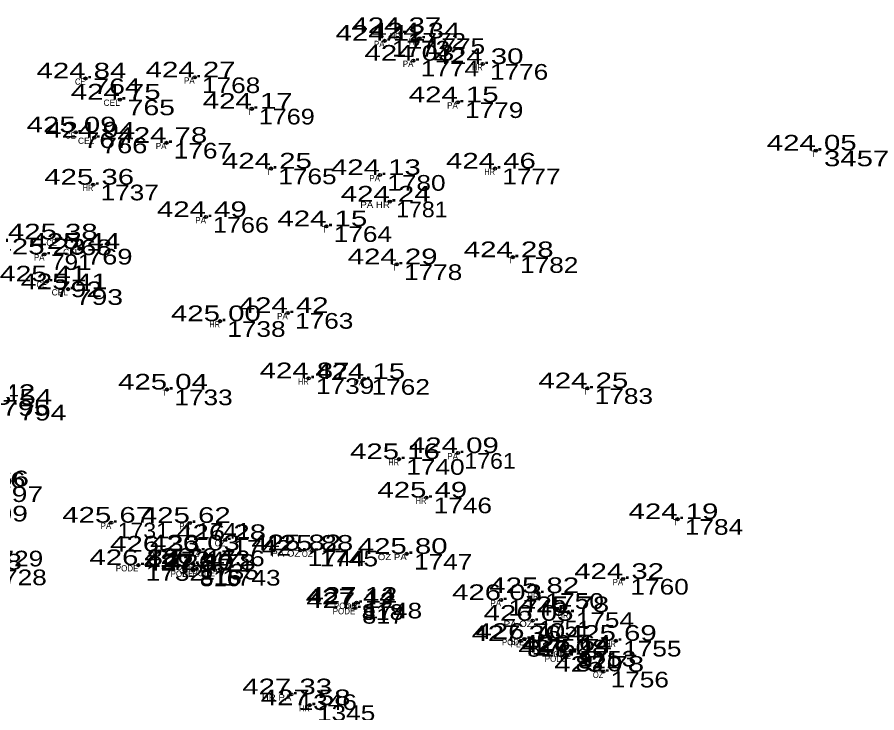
# Model space of a CAD drawing. Extents: x -639390 to -639074, y -1138747 to -1138358.
# Drawn here: x -639242.68 to -639201.57, y -1138603.62 to -1138570.35 of the extents above; entities that cross this region are included whole.
import ezdxf
from ezdxf.enums import TextEntityAlignment as Align

# ---------------------------------------------------------------- set-up
doc = ezdxf.new("R2010")
doc.units = 0
doc.header["$LTSCALE"] = 0.3
doc.header["$PDMODE"] = 32
doc.header["$PDSIZE"] = 0.15
for name, color, linetype in [('11', 7, 'Continuous'), ('12', 7, 'Continuous'), ('13', 7, 'Continuous'), ('57', 7, 'Continuous')]:
    doc.layers.add(name, color=color, linetype=linetype)

msp = doc.modelspace()

# ---------------------------------------------------------------- linework, layer by layer
at = {"layer": '11'}
for p in [(-639224.35, -1138571.11), (-639223.44, -1138571.36), (-639225.11, -1138571.48), (-639223.73, -1138572.43), (-639220.42, -1138572.59), (-639239.41, -1138573.28), (-639234.19, -1138573.23), (-639237.77, -1138574.29), (-639221.61, -1138574.42), (-639231.46, -1138574.73), (-639239.88, -1138575.86), (-639238.99, -1138576.11), (-639235.54, -1138576.36), (-639204.49, -1138576.73), (-639230.54, -1138577.59), (-639219.83, -1138577.59), (-639225.33, -1138577.9), (-639239.04, -1138578.36), (-639224.86, -1138579.17), (-639233.65, -1138579.91), (-639227.89, -1138580.35), (-639240.78, -1138580.98), (-639241.37, -1138581.69), (-639239.7, -1138581.43), (-639218.98, -1138581.83), (-639224.53, -1138582.17), (-639241.25, -1138582.99), (-639240.25, -1138583.36), (-639229.74, -1138584.5), (-639232.98, -1138584.89), (-639228.74, -1138587.62), (-639226.08, -1138587.66), (-639235.51, -1138588.16), (-639215.41, -1138588.1), (-639224.42, -1138591.49), (-639221.6, -1138591.2), (-639223.11, -1138593.33), (-639211.1, -1138594.36), (-639238.18, -1138594.53), (-639234.42, -1138594.54), (-639232.73, -1138595.36), (-639235.89, -1138595.91), (-639233.98, -1138595.86), (-639229.14, -1138595.85), (-639228.56, -1138595.87), (-639224.05, -1138596.02), (-639234.26, -1138596.5), (-639236.88, -1138596.56), (-639234.28, -1138596.76), (-639234.26, -1138596.82), (-639233.22, -1138596.79), (-639213.7, -1138597.22), (-639217.76, -1138597.9), (-639226.54, -1138598.43), (-639226.45, -1138598.36), (-639219.54, -1138598.23), (-639226.51, -1138598.61), (-639216.32, -1138598.81), (-639218.03, -1138599.22), (-639218.61, -1138600.19), (-639218.42, -1138600.09), (-639214.05, -1138600.18), (-639216.37, -1138600.89), (-639216.21, -1138600.66), (-639216.2, -1138600.75), (-639214.65, -1138601.66), (-639229.57, -1138602.74), (-639228.69, -1138603.26)]:
    msp.add_point(p, dxfattribs=at)

# ---------------------------------------------------------------- texts
at = {"layer": '12'}
for s, width, p in [('424.37 ', 1.4, (-639224.35, -1138571.11)), ('424.12 ', 1.4, (-639225.11, -1138571.48)), ('424.34 ', 1.4, (-639223.44, -1138571.36)), ('424.03 ', 1.4, (-639223.73, -1138572.43)), ('424.30 ', 1.4, (-639220.42, -1138572.59)), ('424.84 ', 1.4, (-639239.41, -1138573.28)), ('424.27 ', 1.4, (-639234.19, -1138573.23)), ('424.75 ', 1.4, (-639237.77, -1138574.29)), ('424.15 ', 1.4, (-639221.61, -1138574.42)), ('424.17 ', 1.4, (-639231.46, -1138574.73)), ('425.09 ', 1.4, (-639239.88, -1138575.86)), ('424.94 ', 1.4, (-639238.99, -1138576.11)), ('424.78 ', 1.4, (-639235.54, -1138576.36)), ('424.05 ', 1.4, (-639204.49, -1138576.73)), ('424.25 ', 1.4, (-639230.54, -1138577.59)), ('424.46 ', 1.4, (-639219.829, -1138577.59)), ('424.13 ', 1.4, (-639225.33, -1138577.9)), ('425.36 ', 1.4, (-639239.039, -1138578.36)), ('424.24 ', 1.4, (-639224.86, -1138579.17)), ('424.49 ', 1.4, (-639233.65, -1138579.91)), ('424.15 ', 1.4, (-639227.89, -1138580.35)), ('425.38 ', 1.4, (-639240.78, -1138580.98)), ('425.44 ', 1.4, (-639239.7, -1138581.43)), ('425.23 ', 1.4, (-639241.37, -1138581.69)), ('424.28 ', 1.4, (-639218.98, -1138581.83)), ('424.29 ', 1.4, (-639224.53, -1138582.17)), ('425.41 ', 1.35, (-639241.249, -1138582.99)), ('425.41 ', 1.35, (-639240.249, -1138583.36)), ('424.42 ', 1.4, (-639229.74, -1138584.5)), ('425.00 ', 1.4, (-639232.98, -1138584.89)), ('424.87 ', 1.4, (-639228.74, -1138587.62)), ('424.15 ', 1.4, (-639226.08, -1138587.66)), ('424.25 ', 1.4, (-639215.41, -1138588.1)), ('425.04 ', 1.4, (-639235.51, -1138588.16)), ('425.42 ', 1.4, (-639243.77, -1138588.66)), ('425.54 ', 1.4, (-639242.96, -1138588.89)), ('424.09 ', 1.4, (-639221.6, -1138591.2)), ('425.16 ', 1.4, (-639224.419, -1138591.49)), ('425.66 ', 1.4, (-639244.069, -1138592.79)), ('425.49 ', 1.4, (-639223.11, -1138593.33)), ('425.67 ', 1.4, (-639238.18, -1138594.53)), ('425.62 ', 1.4, (-639234.42, -1138594.54)), ('424.19 ', 1.4, (-639211.1, -1138594.36)), ('426.28 ', 1.4, (-639232.73, -1138595.36)), ('426.33 ', 1.4, (-639235.89, -1138595.91)), ('426.03 ', 1.4, (-639233.98, -1138595.86)), ('425.82 ', 1.4, (-639229.14, -1138595.85)), ('425.88 ', 1.4, (-639228.56, -1138595.87)), ('425.80 ', 1.4, (-639224.05, -1138596.02)), ('426.68 ', 1.4, (-639244.4, -1138596.77)), ('426.88 ', 1.4, (-639236.88, -1138596.56)), ('427.40 ', 1.4, (-639234.28, -1138596.76)), ('426.64 ', 1.4, (-639234.26, -1138596.5)), ('427.30 ', 1.4, (-639234.26, -1138596.82)), ('426.78 ', 1.4, (-639233.22, -1138596.79)), ('424.32 ', 1.4, (-639213.7, -1138597.22)), ('425.82 ', 1.4, (-639217.76, -1138597.9)), ('427.12 ', 1.4, (-639226.45, -1138598.36)), ('426.03 ', 1.4, (-639219.54, -1138598.23)), ('427.44 ', 1.4, (-639226.54, -1138598.43)), ('427.12 ', 1.4, (-639226.51, -1138598.61)), ('425.78 ', 1.4, (-639216.32, -1138598.81)), ('426.05 ', 1.4, (-639218.03, -1138599.22)), ('427.36 ', 1.4, (-639218.609, -1138600.19)), ('426.70 ', 1.4, (-639218.42, -1138600.09)), ('425.69 ', 1.4, (-639214.05, -1138600.18)), ('427.08 ', 1.4, (-639216.37, -1138600.89)), ('426.64 ', 1.4, (-639216.21, -1138600.66)), ('427.14 ', 1.4, (-639216.2, -1138600.75)), ('425.78 ', 1.4, (-639214.65, -1138601.66)), ('427.33 ', 1.4, (-639229.57, -1138602.74)), ('427.58 ', 1.4, (-639228.69, -1138603.26))]:
    msp.add_text(s, height=0.75, dxfattribs=dict(at, width=width)).set_placement(p, align=Align.CENTER)
at = {"layer": '13'}
for s, width, p in [(' 1772', 1.25, (-639224.35, -1138571.86)), (' 1775', 1.25, (-639223.44, -1138572.11)), (' 1773', 1.25, (-639225.11, -1138572.23)), (' 1774', 1.25, (-639223.73, -1138573.18)), (' 1776', 1.25, (-639220.42, -1138573.34)), (' 764', 1.35, (-639239.41, -1138574.03)), (' 1768', 1.25, (-639234.19, -1138573.98)), (' 765', 1.35, (-639237.77, -1138575.04)), (' 1779', 1.25, (-639221.61, -1138575.17)), (' 1769', 1.2, (-639231.46, -1138575.48)), (' 767', 1.35, (-639239.88, -1138576.61)), (' 766', 1.3, (-639238.99, -1138576.86)), (' 1767', 1.25, (-639235.54, -1138577.11)), (' 3457', 1.4, (-639204.49, -1138577.48)), (' 1765', 1.25, (-639230.54, -1138578.34)), (' 1780', 1.25, (-639225.33, -1138578.65)), (' 1777', 1.25, (-639219.83, -1138578.34)), (' 1737', 1.25, (-639239.04, -1138579.11)), (' 1781', 1.1, (-639224.86, -1138579.92)), (' 1766', 1.2, (-639233.65, -1138580.66)), (' 1764', 1.25, (-639227.89, -1138581.1)), (' 768', 1.35, (-639240.78, -1138581.73)), (' 769', 1.3, (-639239.7, -1138582.18)), (' 791', 1.15, (-639241.37, -1138582.44)), (' 1782', 1.25, (-639218.98, -1138582.58)), (' 1778', 1.25, (-639224.53, -1138582.92)), (' 792', 1.35, (-639241.25, -1138583.74)), (' 793', 1.35, (-639240.25, -1138584.11)), (' 1763', 1.25, (-639229.74, -1138585.25)), (' 1738', 1.25, (-639232.98, -1138585.64)), (' 1739', 1.25, (-639228.74, -1138588.37)), (' 1762', 1.25, (-639226.08, -1138588.41)), (' 1733', 1.25, (-639235.51, -1138588.91)), (' 1783', 1.25, (-639215.41, -1138588.85)), (' 795', 1.35, (-639243.77, -1138589.41)), (' 794', 1.35, (-639242.96, -1138589.64)), (' 1740', 1.25, (-639224.42, -1138592.24)), (' 1761', 1.1, (-639221.6, -1138591.95)), (' 796', 1.3, (-639244.82, -1138592.86)), (' 797', 1.35, (-639244.07, -1138593.54)), (' 1746', 1.25, (-639223.11, -1138594.08)), (' 809', 1.35, (-639244.8, -1138594.47)), (' 1784', 1.25, (-639211.1, -1138595.11)), (' 1731', 1.1, (-639238.18, -1138595.28)), (' 1741', 1.15, (-639234.42, -1138595.29)), (' 1742', 1.25, (-639232.73, -1138596.11)), (' 1729', 1.25, (-639244.57, -1138596.62)), (' 1734', 1.25, (-639235.89, -1138596.66)), (' 1736', 1.25, (-639233.98, -1138596.61)), (' 1744', 1.25, (-639229.14, -1138596.6)), (' 1745', 1.25, (-639228.56, -1138596.62)), (' 1747', 1.25, (-639224.05, -1138596.77)), (' 1728', 1.25, (-639244.4, -1138597.52)), (' 1732', 1.25, (-639236.88, -1138597.31)), (' 815', 1.2, (-639234.28, -1138597.51)), (' 816', 1.15, (-639234.26, -1138597.57)), (' 1735', 1.25, (-639234.26, -1138597.25)), (' 1743', 1.25, (-639233.22, -1138597.54)), (' 1760', 1.25, (-639213.7, -1138597.97)), (' 1750', 1.25, (-639217.76, -1138598.65)), (' 818', 1.2, (-639226.54, -1138599.18)), (' 1748', 1.25, (-639226.45, -1138599.11)), (' 1749', 1.25, (-639219.54, -1138598.98)), (' 817', 1.2, (-639226.51, -1138599.36)), (' 1754', 1.25, (-639216.32, -1138599.56)), (' 1751', 1.1, (-639218.03, -1138599.97)), (' 1752', 1.25, (-639218.42, -1138600.84)), (' 819', 1.15, (-639218.61, -1138600.94)), (' 1755', 1.25, (-639214.05, -1138600.93)), (' 820', 1.35, (-639216.37, -1138601.64)), (' 821', 1.2, (-639216.2, -1138601.5)), (' 1753', 1.25, (-639216.21, -1138601.41)), (' 1756', 1.25, (-639214.65, -1138602.41)), (' 1346', 1.25, (-639229.57, -1138603.49)), (' 1345', 1.25, (-639228.69, -1138604.01))]:
    msp.add_text(s, height=0.75, dxfattribs=dict(at, width=width)).set_placement(p)
at = {"layer": '57'}
for s, width, p in [('HR', 0.85, (-639224.349, -1138571.41)), ('HR', 0.85, (-639223.439, -1138571.66)), ('PA', 0.95, (-639225.11, -1138571.78)), ('PA', 0.95, (-639223.73, -1138572.73)), ('HR', 0.85, (-639220.419, -1138572.89)), ('CE', 0.9, (-639239.41, -1138573.58)), ('PA', 0.95, (-639234.19, -1138573.53)), ('PA', 0.95, (-639221.61, -1138574.72)), ('T', 0.85, (-639231.46, -1138575.03)), ('CE', 0.9, (-639239.88, -1138576.16)), ('PA', 0.95, (-639235.54, -1138576.66)), ('T', 0.85, (-639204.49, -1138577.03)), ('T', 0.85, (-639230.54, -1138577.89)), ('PA', 0.95, (-639225.33, -1138578.2)), ('HR', 0.85, (-639219.829, -1138577.89)), ('HR', 0.85, (-639239.039, -1138578.66)), ('PA HR', 1.15, (-639224.859, -1138579.47)), ('PA', 0.95, (-639233.65, -1138580.21)), ('T', 0.85, (-639227.89, -1138580.65)), ('CE', 0.9, (-639240.78, -1138581.28)), ('PA', 0.95, (-639241.37, -1138581.99)), ('T', 0.85, (-639218.98, -1138582.13)), ('T', 0.85, (-639224.53, -1138582.47)), ('CE', 0.9, (-639241.25, -1138583.29)), ('PA', 0.95, (-639229.74, -1138584.8)), ('HR', 0.85, (-639232.979, -1138585.19)), ('HR', 0.85, (-639228.739, -1138587.92)), ('PA', 0.95, (-639226.08, -1138587.96)), ('T', 0.85, (-639235.51, -1138588.46)), ('T', 0.85, (-639215.41, -1138588.4)), ('HR', 0.85, (-639224.419, -1138591.79)), ('PA', 0.95, (-639221.6, -1138591.5)), ('HR', 0.85, (-639223.109, -1138593.63)), ('T', 0.85, (-639211.1, -1138594.66)), ('PA', 0.95, (-639238.18, -1138594.83)), ('PA', 0.95, (-639234.42, -1138594.84)), ('OZ', 0.9, (-639232.729, -1138595.66)), ('OZ', 0.9, (-639235.889, -1138596.21)), ('OZ', 0.9, (-639233.979, -1138596.16)), ('PA OZ', 1.15, (-639229.139, -1138596.15)), ('OZ', 0.9, (-639228.559, -1138596.17)), ('OZ PA', 1.15, (-639224.05, -1138596.32)), ('PODE', 0.95, (-639236.88, -1138596.86)), ('PODE', 0.95, (-639234.26, -1138596.8)), ('PODE', 0.95, (-639234.26, -1138597.12)), ('PODE', 0.95, (-639233.22, -1138597.09)), ('PA', 0.95, (-639213.7, -1138597.52)), ('HR', 0.85, (-639217.759, -1138598.2)), ('PODE', 0.95, (-639226.45, -1138598.66)), ('PA', 0.95, (-639219.54, -1138598.53)), ('PODE', 0.95, (-639226.51, -1138598.91)), ('HR', 0.85, (-639216.319, -1138599.11)), ('PA OZ', 1.15, (-639218.029, -1138599.52)), ('PODE', 0.95, (-639218.42, -1138600.39)), ('HR', 0.85, (-639214.049, -1138600.48)), ('PODE', 0.95, (-639216.37, -1138601.19)), ('PODE', 0.95, (-639216.21, -1138600.96)), ('OZ', 0.9, (-639214.649, -1138601.96)), ('HR PA', 1.15, (-639229.57, -1138603.04)), ('HR', 0.85, (-639228.689, -1138603.56))]:
    msp.add_text(s, height=0.3, dxfattribs=dict(at, width=width)).set_placement(p, align=Align.RIGHT)
for s, p in [('CEL', (-639237.769, -1138574.59)), ('CEL', (-639238.989, -1138576.41)), ('CEL', (-639239.699, -1138581.73)), ('CEL', (-639240.249, -1138583.66)), ('PL', (-639234.279, -1138597.06)), ('PL', (-639226.539, -1138598.73)), ('PL', (-639218.609, -1138600.49)), ('PL', (-639216.199, -1138601.05))]:
    msp.add_text(s, height=0.3, dxfattribs=at).set_placement(p, align=Align.RIGHT)

doc.saveas('drawing.dxf')
